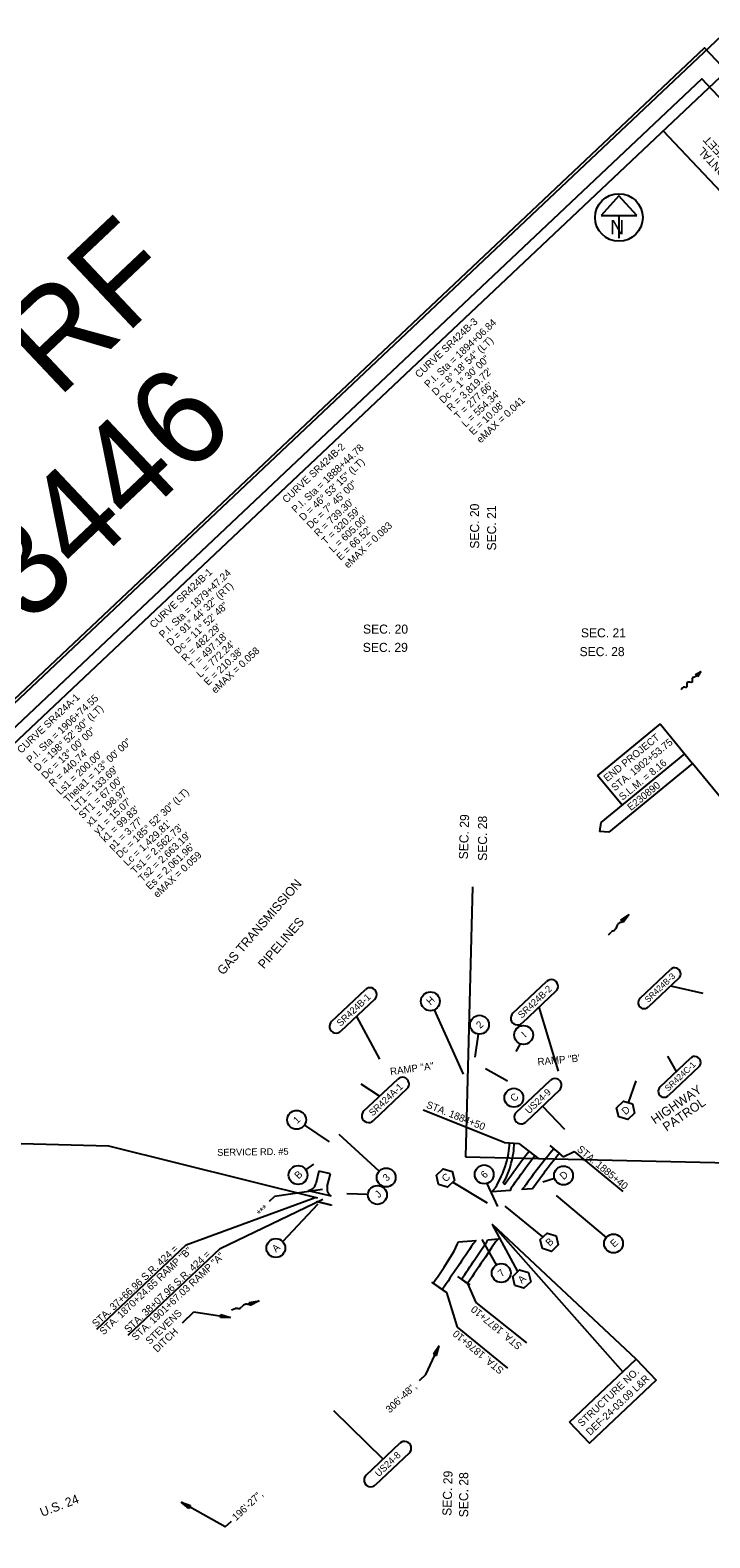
# Model space of a CAD drawing. Extents: x -192968533 to 1447163, y -403992248 to 597737.
# Drawn here: x 1439025 to 1442541, y 589939 to 597737 of the extents above; entities that cross this region are included whole.
import ezdxf

# ---------------------------------------------------------------- set-up
doc = ezdxf.new("R2010")
doc.units = 0
for name, color, linetype in [('DV_X_Corp_Line', 7, 'Continuous'), ('HY_X_Wetland_Area', 7, 'Continuous'), ('Level 21', 7, 'Continuous'), ('Level 31', 7, 'Continuous'), ('Level 56', 7, 'Continuous'), ('Level 63', 7, 'Continuous'), ('RS_Raster1', 7, 'Continuous'), ('RW_X_CL_500_Stations', 7, 'Continuous'), ('RW_X_Esmt_PB', 7, 'Continuous'), ('RW_X_Fee_RW', 7, 'Continuous'), ('SC_Scratch1', 7, 'Continuous'), ('SC_Shading2', 7, 'Continuous'), ('SH_Masking', 7, 'Continuous'), ('SH_Text', 7, 'Continuous')]:
    doc.layers.add(name, color=color, linetype=linetype)

msp = doc.modelspace()

# ---------------------------------------------------------------- linework, layer by layer
at = {"layer": 'DV_X_Corp_Line'}
for p, q in [((1441313.2, 593305.6), (1441276.1, 591910.7)), ((1441276.1, 591910.7), (1442724, 591876.8))]:
    msp.add_line(p, q, dxfattribs=at)
at = {"layer": 'HY_X_Wetland_Area'}
for p, q in [((1442070.2, 596880.4), (1441977.9, 596778)), ((1442162.5, 596778), (1442070.2, 596880.4)), ((1441977.9, 596778), (1442162.5, 596778)), ((1442070.2, 596778), (1442070.2, 596662)), ((1442283.2, 594148.6), (1441959.4, 593883)), ((1442283.2, 594148.6), (1442451.3, 593943.7)), ((1442410.1, 593993.9), (1441977.1, 593638.8)), ((1442410.1, 593993.9), (1441977.1, 593638.8)), ((1442451.3, 593943.7), (1442018.3, 593588.5)), ((1443096.1, 593157.6), (1442451.3, 593943.7)), ((1442086.3, 593728.3), (1441959.4, 593883)), ((1441977.1, 593638.8), (1441970.2, 593591.9)), ((1442018.3, 593588.5), (1441970.2, 593591.9)), ((1442179.6, 592731), (1442336.6, 592879.2)), ((1440584.4, 592610.6), (1440758.9, 592775.3)), ((1441521.8, 592652.8), (1441696.3, 592817.5)), ((1442379.9, 592833.4), (1442222.8, 592685.1)), ((1442337.7, 592793.6), (1442503.6, 592757.2)), ((1442379.9, 592833.4), (1442379.9, 592833.4)), ((1440807, 592724.4), (1440632.4, 592559.7)), ((1440807, 592724.4), (1440807, 592724.4)), ((1441744.4, 592766.6), (1441569.9, 592601.9)), ((1441744.4, 592766.6), (1441744.4, 592766.6)), ((1440713, 592635.7), (1440832.1, 592416)), ((1441115.2, 592669.9), (1441265.6, 592337.2)), ((1441757.3, 592353.5), (1441657.1, 592684.2)), ((1441342.7, 592545.1), (1441325.8, 592425.5)), ((1441558.8, 592495.2), (1441537.7, 592454.8)), ((1442283.6, 592272.3), (1442440.7, 592420.5)), ((1442367.8, 592351.8), (1442323.4, 592430.6)), ((1440751.6, 592147.4), (1440926.1, 592312.2)), ((1441494.9, 592301.5), (1441379.6, 592366)), ((1441540.2, 592140.6), (1441714.7, 592305.3)), ((1442119.1, 592189.9), (1442160, 592303.8)), ((1442483.9, 592374.7), (1442326.8, 592226.4)), ((1442483.9, 592374.7), (1442483.9, 592374.7)), ((1440832.8, 592224.1), (1440737.9, 592286.7)), ((1440974.1, 592261.3), (1440799.6, 592096.5)), ((1440974.1, 592261.3), (1440974.1, 592261.3)), ((1441762.7, 592254.4), (1441588.2, 592089.7)), ((1441762.7, 592254.4), (1441762.7, 592254.4)), ((1441477.2, 591984), (1441057.8, 592152)), ((1441675.5, 592172), (1441788.1, 592052.9)), ((1440443.7, 592073.9), (1440571.2, 591987.9)), ((1438457.5, 591993.2), (1439431, 591966.4)), ((1440830.7, 591836.1), (1440623, 592026.2)), ((1439431, 591966.4), (1440511.8, 591697.3)), ((1441477.2, 591984), (1441552.6, 591979.8)), ((1441552.6, 591979.8), (1441656.5, 591898.9)), ((1441713.3, 591968.7), (1441762.2, 591927.4)), ((1441762.2, 591927.4), (1441782.7, 591910.1)), ((1441782.7, 591910.1), (1441839.2, 591938.4)), ((1441839.2, 591938.4), (1442091, 591731.2)), ((1440451.1, 591843.4), (1440492, 591871.3)), ((1441210.6, 591778.3), (1441389.1, 591671.8)), ((1441387.2, 591772.3), (1441441.7, 591652.6)), ((1441737.4, 591798.8), (1441677.2, 591779.5)), ((1439832.5, 591455.6), (1440499.6, 591700.4)), ((1440007.6, 591436.2), (1440539.4, 591690.5)), ((1440263.3, 591680.2), (1440288.6, 591704.1)), ((1440536.8, 591741.5), (1440288.6, 591704.1)), ((1440772.7, 591714.6), (1440663.4, 591718.2)), ((1442005.2, 591493.2), (1441747, 591710.5)), ((1440331.5, 591471.9), (1440515.2, 591667)), ((1441676.9, 591495.5), (1441481.2, 591655.6)), ((1441546.9, 591316.2), (1441416.4, 591559.9)), ((1439370, 591019), (1439832.5, 591455.6)), ((1441437.6, 591351.6), (1441363.7, 591481.9)), ((1439533.2, 590988.4), (1440007.6, 591436.2)), ((1441234.7, 591291.1), (1441287.6, 591255.1)), ((1441110.3, 591255.9), (1441178, 591208.7)), ((1441178, 591208.7), (1441234.1, 591029.5)), ((1441287.6, 591255.1), (1441331, 591156.7)), ((1441331, 591156.7), (1441591.6, 590947.3)), ((1441234.1, 591029.5), (1441494.9, 590817.4)), ((1441070.9, 590784.1), (1441140.5, 590933.4)), ((1441140.1, 590933.1), (1441110.9, 590889.7)), ((1441126.5, 590882.6), (1441140.1, 590933.1)), ((1441110.9, 590889.7), (1441126.5, 590882.6)), ((1441070.9, 590784.1), (1441037.3, 590752.3)), ((1440850.3, 590346.1), (1440595.5, 590595.6)), ((1440763, 590263.8), (1440937.6, 590428.5)), ((1440985.6, 590377.6), (1440811.1, 590212.9)), ((1440985.6, 590377.6), (1440985.6, 590377.6)), ((1440034.8, 589995.8), (1439805.9, 590124.3)), ((1439846.6, 590091.6), (1439805.9, 590124.3)), ((1439805.9, 590124.3), (1439855, 590106.5)), ((1439855, 590106.5), (1439846.6, 590091.6)), ((1440034.8, 589995.8), (1440066.8, 590026))]:
    msp.add_line(p, q, dxfattribs=at)
for points in [[(1442069.3, 592116.6), (1442058.1, 592164.1), (1442093.5, 592197.5), (1442140.2, 592183.6), (1442151.5, 592136.1), (1442116, 592102.7)], [(1441137.5, 591767.4), (1441126.2, 591814.8), (1441161.7, 591848.3), (1441208.4, 591834.3), (1441219.7, 591786.8), (1441184.2, 591753.4)], [(1442160.3, 590863.7), (1441416.4, 591559.9), (1442090.1, 590797.5)], [(1441674.4, 591435.1), (1441663.2, 591482.5), (1441698.6, 591516), (1441745.3, 591502), (1441756.6, 591454.6), (1441721.1, 591421.1)], [(1441532.1, 591244.2), (1441520.9, 591291.7), (1441556.3, 591325.1), (1441603, 591311.1), (1441614.3, 591263.7), (1441578.8, 591230.3)], [(1441815.2, 590538), (1442160.3, 590863.7), (1442263.2, 590754.6), (1441918.1, 590428.9)]]:
    msp.add_lwpolyline(points, close=True, dxfattribs=at)
for centre, radius in [((1442070.2, 596768.2), 123), ((1441095.1, 592714.3), 48.8), ((1441349.5, 592593.4), 48.8), ((1441577.6, 592540.2), 48.8), ((1441526.9, 592215.6), 48.8), ((1440403.3, 592101.2), 48.8), ((1440410.8, 591816), 48.8), ((1440866.7, 591803.2), 48.8), ((1441373.7, 591819.1), 48.8), ((1441783.8, 591813.8), 48.8), ((1440821.4, 591713), 48.8), ((1440296, 591438.4), 48.8), ((1442042.5, 591461.8), 48.8), ((1441461.7, 591309.2), 48.8)]:
    msp.add_circle(centre, radius, dxfattribs=at)
for centre, radius, start, end in [((1442358.3, 592856.3), 31.5, 313.34418, 133.3446), ((1440783, 592749.9), 35, 313.34418, 133.3446), ((1441720.4, 592792), 35, 313.34418, 133.3446), ((1442201.2, 592708.1), 31.5, 133.3446, 313.34502), ((1441545.8, 592627.3), 35, 133.3446, 313.34502), ((1440608.4, 592585.2), 35, 133.3446, 313.34502), ((1442462.3, 592397.6), 31.5, 313.34418, 133.3446), ((1440950.1, 592286.7), 35, 313.34418, 133.3446), ((1441738.7, 592279.8), 35, 313.34418, 133.3446), ((1442305.2, 592249.3), 31.5, 133.3446, 313.34502), ((1440775.6, 592122), 35, 133.3446, 313.34502), ((1441564.2, 592115.1), 35, 133.3446, 313.34502), ((1440961.6, 590403), 35, 313.34418, 133.3446), ((1440787.1, 590238.3), 35, 133.3446, 313.34502)]:
    msp.add_arc(centre, radius, start, end, dxfattribs=at)
at = {"layer": 'Level 21'}
msp.add_spline([(1440507.4, 591679.9), (1440510.1, 591679.2), (1440512.8, 591678.5), (1440515.5, 591677.9), (1440518.2, 591677.2), (1440520.9, 591676.5), (1440523.6, 591675.9), (1440526.3, 591675.2), (1440529, 591674.5), (1440531.7, 591673.8), (1440534.4, 591673.2), (1440537, 591672.5), (1440539.7, 591671.8), (1440542.4, 591671.2), (1440545.1, 591670.5), (1440547.8, 591669.9), (1440550.5, 591669.2), (1440553.2, 591668.5), (1440555.9, 591667.9), (1440558.6, 591667.2), (1440561.3, 591666.5), (1440564, 591665.9), (1440566.7, 591665.2), (1440569.4, 591664.6), (1440572.1, 591663.9), (1440574.8, 591663.3), (1440577.5, 591662.6), (1440580.2, 591662), (1440582.9, 591661.3), (1440584.6, 591660.9)], degree=3, dxfattribs=at)
at = {"layer": 'Level 31'}
for p, q in [((1442079.9, 593133.2), (1442122.5, 593163.6)), ((1442085, 593126.2), (1442122.5, 593163.6)), ((1442122.5, 593163.6), (1442092.1, 593121.1)), ((1442058, 593098.9), (1442054.9, 593091.2)), ((1442061.6, 593107.5), (1442058, 593098.9)), ((1442077.8, 593121.3), (1442073.7, 593119.6)), ((1442092.1, 593121.1), (1442079.9, 593133.2)), ((1442016, 593057.9), (1442030.8, 593072.7)), ((1442042, 593078.7), (1442037.7, 593077.1)), ((1440122.3, 591136.2), (1440116, 591130.8)), ((1440129.4, 591142.2), (1440122.3, 591136.2)), ((1440150.1, 591147.2), (1440145.7, 591147.5)), ((1440157.4, 591156.8), (1440209.1, 591164.5)), ((1440162.7, 591140.5), (1440157.4, 591156.8)), ((1440158.7, 591148.2), (1440209.1, 591164.5)), ((1440209.1, 591164.5), (1440162.7, 591140.5)), ((1440066.2, 591118.9), (1440086.1, 591125.3)), ((1440098.8, 591125.6), (1440094.2, 591126.1))]:
    msp.add_line(p, q, dxfattribs=at)
for centre, radius, start, end in [((1442034.2, 593099.7), 22.4, 290.49742, 337.60588), ((1442082.3, 593098.9), 22.4, 112.63126, 157.47511), ((1442069.2, 593142), 22.4, 292.67009, 315.03011), ((1442044.4, 593059.1), 19.2, 110.54729, 135.03011), ((1440101.4, 591147.8), 22.4, 263.39329, 310.50176), ((1440143.9, 591125.2), 22.4, 85.52713, 130.37099), ((1440151.8, 591169.5), 22.4, 265.56596, 287.92598), ((1440092, 591107), 19.2, 83.44317, 107.92598)]:
    msp.add_arc(centre, radius, start, end, dxfattribs=at)
at = {"layer": 'Level 56'}
for p, q in [((1442465.5, 594405.1), (1442494.6, 594420.9)), ((1442477.3, 594392.6), (1442465.5, 594405.1)), ((1442494.6, 594420.9), (1442477.3, 594392.6))]:
    msp.add_line(p, q, dxfattribs=at)
msp.add_spline([(1442471.3, 594398.9), (1442470.4, 594398.1), (1442458.8, 594391.2), (1442450.7, 594387.6), (1442448.5, 594365.2), (1442423.1, 594363.9), (1442418.2, 594336.5), (1442408.8, 594339.8), (1442393, 594324.5)], degree=3, dxfattribs=at)
at = {"layer": 'Level 63'}
for points in [[(1435095.9, 590645), (1442513.2, 597645.6), (1447042.8, 592846.4), (1439625.5, 585845.8)], [(1439613.4, 586032.4), (1446856.7, 592868.7), (1442499.5, 597485.3), (1435256.2, 590648.9)]]:
    msp.add_lwpolyline(points, close=True, dxfattribs=at)
at = {"layer": 'RW_X_CL_500_Stations'}
msp.add_lwpolyline([(1439744.7, 585936.1), (1447162.5, 592937.2), (1442632.4, 597737), (1435214.5, 590735.9)], close=True, dxfattribs=at)
at = {"layer": 'RW_X_Esmt_PB'}
msp.add_line((1446623.2, 592634.5), (1442299, 597216.1), dxfattribs=at)
msp.add_lwpolyline([(1435644.7, 590935.7), (1442626.2, 597525), (1446950.5, 592943.4), (1439969, 586354.1)], close=True, dxfattribs=at)
at = {"layer": 'SC_Scratch1'}
for p, q in [((1441713.3, 591968.7), (1441782.7, 591910.1)), ((1441507.9, 591736.4), (1441415.3, 591729.3)), ((1441512, 591746.2), (1441507.9, 591736.4)), ((1441234.7, 591291.1), (1441298.6, 591247.6)), ((1441178, 591208.7), (1441102.8, 591261.1))]:
    msp.add_line(p, q, dxfattribs=at)
msp.add_arc((1445427.3, 589015.9), 4773.3, 144.04703, 145.10999, dxfattribs=at)
at = {"layer": 'SC_Shading2'}
for p, q in [((1441504.4, 591982.5), (1441529.3, 591981.1)), ((1441606, 591938.2), (1441636, 591914.9)), ((1441733.2, 591951.9), (1441762.2, 591927.4)), ((1440519, 591836.2), (1440502.5, 591769.7)), ((1440578.2, 591821.5), (1440519, 591836.2)), ((1441698.5, 591848.7), (1441683.2, 591828.8)), ((1441714.7, 591869.3), (1441698.5, 591848.7)), ((1441737, 591897.1), (1441714.7, 591869.3)), ((1440562, 591756.3), (1440578.2, 591821.5)), ((1441472.3, 591773.1), (1441480.4, 591767.4)), ((1441567.7, 591741), (1441581.9, 591755.1)), ((1441679.7, 591822.1), (1441623.2, 591745.3)), ((1441683.2, 591828.8), (1441679.7, 591822.1)), ((1441679.7, 591822.1), (1441679.7, 591822.1)), ((1440462.3, 591736.4), (1440581.8, 591708.1)), ((1441415.3, 591729.3), (1441421.9, 591740.1)), ((1441421.9, 591740.1), (1441429.2, 591747.1)), ((1441623.2, 591745.3), (1441567.7, 591741)), ((1441226.7, 591440.8), (1441233.9, 591457.3)), ((1441233.9, 591457.3), (1441240, 591469.9)), ((1441233.9, 591457.3), (1441233.9, 591457.3)), ((1441240, 591469.9), (1441332.6, 591477)), ((1441332.6, 591477), (1441317.1, 591459.4)), ((1441356.6, 591425), (1441386.9, 591469.8)), ((1441386.9, 591469.8), (1441392.4, 591481.6)), ((1441392.4, 591481.6), (1441447.8, 591485.9)), ((1441434, 591471.6), (1441412.1, 591439.2)), ((1441447.8, 591485.9), (1441434, 591471.6)), ((1441447.8, 591485.9), (1441447.8, 591485.9)), ((1441165.9, 591340), (1441197.6, 591389.3)), ((1441197.6, 591389.3), (1441218.8, 591422.4)), ((1441218.8, 591422.4), (1441226.7, 591440.8)), ((1441325.5, 591379), (1441356.6, 591425)), ((1441412.1, 591439.2), (1441380.1, 591391.8)), ((1441156.7, 591223.5), (1441110.3, 591255.9)), ((1441287.6, 591255.1), (1441256.2, 591276.5))]:
    msp.add_line(p, q, dxfattribs=at)
msp.add_lwpolyline([(1441512, 591746.2), (1441507.9, 591736.4), (1441415.3, 591729.3)], dxfattribs=at)
for centre, radius, start, end in [((1444644.4, 589573.2), 3850.4, 142.10364, 145.25886), ((1441069.9, 591996.8), 434.7, 343.68787, 358.10979), ((1444493.8, 589683.9), 3625.5, 142.02302, 145.33189), ((1441069.9, 591996.8), 459.7, 344.82295, 358.03914), ((1444033, 590027.9), 2998.5, 140.08475, 144.82939), ((1443490, 590467.4), 2262.1, 139.80232, 140.80029), ((1440955, 592039.2), 556.9, 328.37422, 342.82401), ((1441020.4, 592013.5), 511.9, 331.98323, 344.46507), ((1440459.8, 591780.4), 44, 273.36181, 346.02037), ((1440604.7, 591745.7), 44, 166.02037, 238.61881), ((1475926.7, 567747.6), 41953.2, 145.58418, 145.97366), ((1352865.2, 651152.2), 106761.7, 325.886439, 325.952878), ((1525938.1, 534102.2), 102137.9, 145.881625, 145.97422), ((1435901.7, 594761.8), 6278.5, 326.0556, 326.97605)]:
    msp.add_arc(centre, radius, start, end, dxfattribs=at)
at = {"layer": 'SH_Masking'}
msp.add_circle((1442070.2, 596768.2), 123, dxfattribs=at)
at = {"layer": 'SH_Text'}
for p, q in [((1439812.7, 591052), (1439871.8, 591107.8)), ((1439871.8, 591107.8), (1440062.1, 591079.2)), ((1440009.8, 591078.4), (1440012.3, 591095.3)), ((1440062.1, 591079.2), (1440009.8, 591078.4)), ((1440012.3, 591095.3), (1440062.1, 591079.2))]:
    msp.add_line(p, q, dxfattribs=at)

# ---------------------------------------------------------------- texts
at = {"layer": 'HY_X_Wetland_Area'}
for s, height, rotation, p in [('24336GB04.PRF', 500, 43.34458, (1436112.2, 592943.2)), ('N', 75, 0.00095, (1442024.8, 596680.8)), ('CURVE SR424B-3', 37.5, 43.3446, (1441037, 595936.1)), ('P.I. Sta = 1894+06.84', 37.5, 43.3446, (1441085.1, 595885.2)), ('D = 8° 18\' 54" (LT)', 37.5, 43.3446, (1441123.7, 595844.3)), ('Dc = 1° 30\' 00"', 37.5, 43.3446, (1441162.3, 595803.4)), ('ROT=43.3446', 500, 43.34458, (1437031.4, 592779.4)), ("R = 3,819.72'", 37.5, 43.3446, (1441200.9, 595762.5)), ("T = 277.66'", 37.5, 43.3446, (1441239.5, 595721.6)), ("L = 554.34'", 37.5, 43.3446, (1441278.1, 595680.7)), ("E = 10.08'", 37.5, 43.3446, (1441316.7, 595639.8)), ('eMAX = 0.041', 37.5, 43.3446, (1441355.3, 595598.9)), ('CURVE SR424B-2', 37.5, 43.3446, (1440351.1, 595288.7)), ('P.I. Sta = 1888+44.78', 37.5, 43.3446, (1440399.1, 595237.8)), ('D = 46° 53\' 15" (LT)', 37.5, 43.3446, (1440437.7, 595196.9)), ('Dc = 7° 45\' 00"', 37.5, 43.3446, (1440476.3, 595156)), ("R = 739.30'", 37.5, 43.3446, (1440514.9, 595115.1)), ("T = 320.59'", 37.5, 43.3446, (1440553.6, 595074.2)), ("L = 605.00'", 37.5, 43.3446, (1440592.2, 595033.2)), ('eMAX = 0.083', 37.5, 43.3446, (1440669.4, 594951.4)), ("E = 66.52'", 37.5, 43.3446, (1440630.8, 594992.3)), ('CURVE SR424B-1', 37.5, 43.3446, (1439665.1, 594641.3)), ('P.I. Sta = 1879+47.24', 37.5, 43.3446, (1439713.2, 594590.4)), ('D = 91° 44\' 32" (RT)', 37.5, 43.3446, (1439751.8, 594549.5)), ('Dc = 11° 52\' 48"', 37.5, 43.3446, (1439790.4, 594508.5)), ("R = 482.29'", 37.5, 43.3446, (1439829, 594467.6)), ("T = 497.18'", 37.5, 43.3446, (1439867.6, 594426.7)), ("L = 772.24'", 37.5, 43.3446, (1439906.2, 594385.8)), ("E = 210.38'", 37.5, 43.3446, (1439944.8, 594344.9)), ('eMAX = 0.058', 37.5, 43.3446, (1439983.4, 594304)), ('CURVE SR424A-1', 37.5, 43.3446, (1438979.2, 593993.8)), ('P.I. Sta = 1906+74.55', 37.5, 43.3446, (1439027.2, 593942.9)), ('D = 198° 52\' 30" (LT)', 37.5, 43.3446, (1439065.8, 593902)), ('Dc = 13° 00\' 00"', 37.5, 43.3446, (1439104.4, 593861.1)), ('END PROJECT', 37.5, 39.36036, (1442010, 593848)), ("R = 440.74'", 37.5, 43.3446, (1439143, 593820.2)), ('Theta1 = 13° 00\' 00"', 37.5, 43.3446, (1439220.2, 593738.4)), ('STA. 1902+53.75', 37.5, 39.36036, (1442049.6, 593799.7)), ("Ls1 = 200.00'", 37.5, 43.3446, (1439181.6, 593779.3)), ('S.L.M. = 8.16', 37.5, 39.36036, (1442089.2, 593751.3)), ("LT1 = 133.69'", 37.5, 43.3446, (1439258.9, 593697.5)), ("ST1 = 67.00'", 37.5, 43.3446, (1439297.5, 593656.6)), ("x1 = 198.97'", 37.5, 43.3446, (1439336.1, 593615.7)), ('Dc = 185° 52\' 30" (LT)', 37.5, 43.3446, (1439490.5, 593452.1)), ('E230890', 37.5, 39.36036, (1442132.4, 593698)), ("y1 = 15.07'", 37.5, 43.3446, (1439374.7, 593574.8)), ("k1 = 99.83'", 37.5, 43.3446, (1439413.3, 593533.9)), ("p1 = 3.77'", 37.5, 43.3446, (1439451.9, 593493)), ("Lc = 1,429.81'", 37.5, 43.3446, (1439529.1, 593411.1)), ("Ts1 = 2,562.73'", 37.5, 43.3446, (1439567.7, 593370.2)), ("Ts2 = 2,663.19'", 37.5, 43.3446, (1439606.3, 593329.3)), ("Es = 2,061.96'", 37.5, 43.3446, (1439644.9, 593288.4)), ('eMAX = 0.059', 37.5, 43.3446, (1439683.6, 593247.5)), ('SR424B-3', 31.95, 43.3446, (1442221.4, 592705.2)), ('SR424B-2', 35.5, 43.3446, (1441568.2, 592624)), ('SR424B-1', 35.5, 43.3446, (1440630.7, 592581.8)), ('H', 37.5, 43.3446, (1441095.5, 592692.1)), ('2', 37.5, 43.3446, (1441352.7, 592570.6)), ('I', 37.5, 43.3446, (1441586.7, 592524)), ('RAMP "A"', 37.5, 7.81588, (1440889.5, 592332.1)), ('RAMP "B\'', 37.5, 5.19059, (1441651.1, 592383)), ('SR424C-1', 31.95, 43.3446, (1442325.3, 592246.3)), ('SR424A-1', 35.5, 43.3446, (1440797.3, 592118)), ('C', 37.5, 43.3446, (1441528.9, 592191.7)), ('US24-9', 35.5, 43.3446, (1441605.5, 592129.7)), ('HIGHWAY', 46.8, 34.45442, (1442256.4, 592077.4)), ('STA. 1884+50', 37.5, 338.29005, (1441070.5, 592165.2)), ('D', 37.5, 43.3446, (1442105.4, 592124.9)), ('PATROL', 46.8, 34.45442, (1442317.1, 592039.5)), ('1', 37.5, 43.3446, (1440406.5, 592078.4)), ('SERVICE RD. #5', 35.5, 0.84353, (1439992.9, 591915.2)), ('STA. 1885+40', 37.5, 320.27792, (1441850.2, 591943.7)), ('B', 37.5, 43.3446, (1440413.2, 591792.5)), ('6', 37.5, 43.3446, (1441376.5, 591796)), ('D', 37.5, 43.3446, (1441784.8, 591788.8)), ('3', 37.5, 43.3446, (1440870, 591780.5)), ('C', 37.5, 43.3446, (1441175, 591776.9)), ('J', 37.5, 43.3446, (1440828.6, 591695)), ('***', 37.5, 43.3446, (1440219.7, 591598.4)), ('STA. 37+66.96 S.R. 424 =', 37.5, 43.3446, (1439366.7, 591026.9)), ('STA. 1870+24.65 RAMP "B"', 37.5, 43.3446, (1439405.3, 590986)), ('A', 37.5, 43.3446, (1440297.2, 591413.8)), ('B', 37.5, 43.3446, (1441712, 591444.8)), ('E', 37.5, 43.3446, (1442046.1, 591439.4)), ('STA. 38+07.96 S.R. 424 =', 37.5, 43.3446, (1439533.3, 590998)), ('STA. 1901+67.03 RAMP "A"', 37.5, 43.3446, (1439571.9, 590957.1)), ('7', 37.5, 43.3446, (1441464.6, 591286.3)), ('A', 37.5, 43.3446, (1441568.4, 591252.7)), ('STA. 1877+10', 37.5, 140.28109, (1441572.3, 590937.6)), ('STA. 1876+10', 37.5, 140.28109, (1441478.5, 590811.4)), ('STRUCTURE NO.', 37.5, 43.3446, (1441878.5, 590511.9)), ('DEF-24-03.09 L&R', 37.5, 43.3446, (1441921.4, 590466.4)), ('306\'-48",', 37.5, 43.3446, (1440885, 590582.4)), ('US24-8', 35.5, 43.3446, (1440828.2, 590252.7)), ('U.S. 24', 46.8, 20.92979, (1439087.2, 590047.5)), ('196\'-27",', 37.5, 43.3446, (1440090.6, 590025.4))]:
    msp.add_text(s, height=height, rotation=rotation, dxfattribs=at).set_placement(p)
at = {"layer": 'RS_Raster1'}
for s, p in [('GAS TRANSMISSION', (1440023.5, 592847.2)), ('PIPELINES', (1440234.5, 592878.8))]:
    msp.add_text(s, height=46.8, rotation=49.10369, dxfattribs=at).set_placement(p)
at = {"layer": 'RW_X_Fee_RW'}
for s, p in [('HORIZONTAL', (1442752.7, 596873.1)), ('SCALE IN FEET', (1442817.7, 596892.7))]:
    msp.add_text(s, height=42, rotation=133.3446, dxfattribs=at).set_placement(p)
at = {"layer": 'SH_Text'}
for s, height, rotation, p in [('SEC. 20', 46.8, 90, (1441347.4, 595055.2)), ('SEC. 21', 46.8, 90, (1441435.3, 595045.9)), ('SEC. 29', 46.8, 88.34647, (1441289.2, 593448)), ('SEC. 28', 46.8, 90, (1441388.4, 593440.7)), ('STEVENS', 37.5, 43.3446, (1439643.6, 590937)), ('DITCH', 37.5, 43.3446, (1439682.2, 590896.1)), ('SEC. 29', 46.8, 88.34647, (1441203.7, 590052.8)), ('SEC. 28', 46.8, 90, (1441290.9, 590045.9))]:
    msp.add_text(s, height=height, rotation=rotation, dxfattribs=at).set_placement(p)
for s, p in [('SEC. 20', (1440746.8, 594616)), ('SEC. 21', (1441873.7, 594596.6)), ('SEC. 29', (1440745.7, 594521.4)), ('SEC. 28', (1441866.7, 594499.5))]:
    msp.add_text(s, height=46.8, dxfattribs=at).set_placement(p)

doc.saveas('drawing.dxf')
